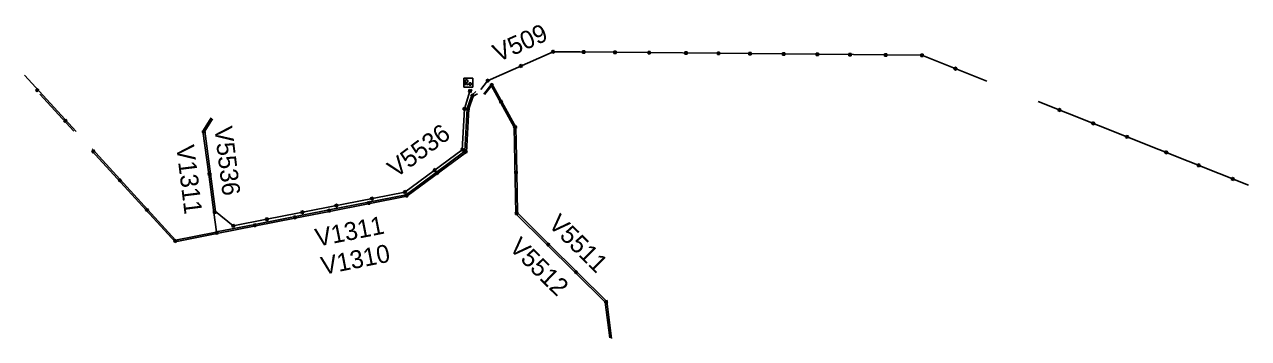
# Model space of a CAD drawing. Extents: x -643369 to -636597, y -1117367 to -1115631.
import ezdxf

# ---------------------------------------------------------------- set-up
doc = ezdxf.new("R2010")
doc.units = 0
for name, color, linetype in [('11', 7, 'Continuous'), ('22', 7, 'Continuous'), ('7', 7, 'Continuous'), ('9', 7, 'Continuous')]:
    doc.layers.add(name, color=color, linetype=linetype)

# ---------------------------------------------------------------- blocks, each defined once
blk = doc.blocks.new('WN200')
at = {"layer": '11'}
for points in [[(-6.3, 6.3), (6.3, 6.3)], [(-6.3, -6.3), (-6.3, 6.3)], [(-4.7, 4.6), (4.7, 4.6)], [(-4.7, -4.8), (-4.7, 4.6)], [(-3.1, 3.2), (3.1, 3.2)], [(-3.1, -3.2), (-3.1, 3.2)], [(-1.6, -1.4), (-1.6, 1.8)], [(-1.6, 1.8), (1.6, 1.8)], [(0, 6.3), (0, 10.1)], [(1.6, 1.8), (1.6, -1.4)], [(3.1, 3.2), (3.1, -3.2)], [(4.7, 4.6), (4.7, -4.8)], [(6.3, 6.3), (6.3, -6.3)], [(6.3, -6.3), (-6.3, -6.3)], [(4.7, -4.8), (-4.7, -4.8)], [(3.1, -3.2), (-3.1, -3.2)], [(1.6, -1.4), (-1.6, -1.4)], [(0, -6.3), (0, -10.1)]]:
    blk.add_lwpolyline(points, dxfattribs=at)
blk = doc.blocks.new('WN600')
at = {"layer": '22'}
for points in [[(25, 25), (-25, 25)], [(-25, 25), (-25, -25)], [(-15.4, 15.4), (-7.1, 15.4)], [(-15.4, -14.2), (-15.4, 15.4)], [(-15.4, 15.4), (-7.1, 15.4)], [(-15.4, -14.2), (-15.4, 15.4)], [(-15.4, 15.4), (-7.1, 15.4)], [(-15.4, -14.2), (-15.4, 15.4)], [(-15.4, 15.4), (-7.1, 15.4)], [(-15.4, -14.2), (-15.4, 15.4)], [(-7.1, 0.4), (-15.4, 0.4)], [(-7.1, 0.4), (-15.4, 0.4)], [(-7.1, 0.4), (-15.4, 0.4)], [(-7.1, 0.4), (-15.4, 0.4)], [(-11.2, 0.4), (-2.1, -14.2)], [(-11.2, 0.4), (-2.1, -14.2)], [(-11.2, 0.4), (-2.1, -14.2)], [(-11.2, 0.4), (-2.1, -14.2)], [(-7.1, 15.4), (-4.6, 13.7)], [(-7.1, 15.4), (-4.6, 13.7)], [(-7.1, 15.4), (-4.6, 13.7)], [(-7.1, 15.4), (-4.6, 13.7)], [(-4.6, 2.5), (-7.1, 0.4)], [(-4.6, 2.5), (-7.1, 0.4)], [(-4.6, 2.5), (-7.1, 0.4)], [(-4.6, 2.5), (-7.1, 0.4)], [(-4.6, 13.7), (-2.1, 10)], [(-4.6, 13.7), (-2.1, 10)], [(-4.6, 13.7), (-2.1, 10)], [(-4.6, 13.7), (-2.1, 10)], [(-2.1, 6.3), (-4.6, 2.5)], [(-2.1, 6.3), (-4.6, 2.5)], [(-2.1, 6.3), (-4.6, 2.5)], [(-2.1, 6.3), (-4.6, 2.5)], [(-2.1, 10), (-2.1, 6.3)], [(-2.1, 10), (-2.1, 6.3)], [(-2.1, 10), (-2.1, 6.3)], [(-2.1, 10), (-2.1, 6.3)], [(25, -25), (25, 25)], [(-25, -25), (25, -25)], [(16.4, -8.3), (16.4, -7.6), (16.3, -6.9), (16.1, -6.2), (15.9, -5.5), (15.6, -4.9), (15.2, -4.3), (14.8, -3.8), (14.3, -3.3), (13.8, -2.9), (13.3, -2.5), (12.7, -2.2), (12.1, -1.9), (11.5, -1.7), (10.8, -1.6), (10.2, -1.6), (9.6, -1.6), (8.9, -1.7), (8.3, -1.9), (7.7, -2.2), (7.1, -2.5), (6.5, -2.9), (6, -3.3), (5.6, -3.8), (5.2, -4.3), (4.8, -4.9), (4.5, -5.5), (4.3, -6.2), (4.1, -6.9), (4, -7.6), (4, -8.3), (4, -9), (4.1, -9.6), (4.3, -10.3), (4.5, -11), (4.8, -11.6), (5.2, -12.2), (5.6, -12.7), (6, -13.2), (6.5, -13.7), (7.1, -14.1), (7.7, -14.4), (8.3, -14.6), (8.9, -14.8), (9.6, -14.9), (10.2, -14.9), (10.8, -14.9), (11.5, -14.8), (12.1, -14.6), (12.7, -14.4), (13.3, -14.1), (13.8, -13.7), (14.3, -13.2), (14.8, -12.7), (15.2, -12.2), (15.6, -11.6), (15.9, -11), (16.1, -10.3), (16.3, -9.6), (16.4, -9), (16.4, -8.3)], [(16.4, -8.3), (16.4, -7.6), (16.3, -6.9), (16.1, -6.2), (15.9, -5.5), (15.6, -4.9), (15.2, -4.3), (14.8, -3.8), (14.3, -3.3), (13.8, -2.9), (13.3, -2.5), (12.7, -2.2), (12.1, -1.9), (11.5, -1.7), (10.8, -1.6), (10.2, -1.6), (9.6, -1.6), (8.9, -1.7), (8.3, -1.9), (7.7, -2.2), (7.1, -2.5), (6.5, -2.9), (6, -3.3), (5.6, -3.8), (5.2, -4.3), (4.8, -4.9), (4.5, -5.5), (4.3, -6.2), (4.1, -6.9), (4, -7.6), (4, -8.3), (4, -9), (4.1, -9.6), (4.3, -10.3), (4.5, -11), (4.8, -11.6), (5.2, -12.2), (5.6, -12.7), (6, -13.2), (6.5, -13.7), (7.1, -14.1), (7.7, -14.4), (8.3, -14.6), (8.9, -14.8), (9.6, -14.9), (10.2, -14.9), (10.8, -14.9), (11.5, -14.8), (12.1, -14.6), (12.7, -14.4), (13.3, -14.1), (13.8, -13.7), (14.3, -13.2), (14.8, -12.7), (15.2, -12.2), (15.6, -11.6), (15.9, -11), (16.1, -10.3), (16.3, -9.6), (16.4, -9), (16.4, -8.3)], [(16.4, -8.3), (16.4, -7.6), (16.3, -6.9), (16.1, -6.2), (15.9, -5.5), (15.6, -4.9), (15.2, -4.3), (14.8, -3.8), (14.3, -3.3), (13.8, -2.9), (13.3, -2.5), (12.7, -2.2), (12.1, -1.9), (11.5, -1.7), (10.8, -1.6), (10.2, -1.6), (9.6, -1.6), (8.9, -1.7), (8.3, -1.9), (7.7, -2.2), (7.1, -2.5), (6.5, -2.9), (6, -3.3), (5.6, -3.8), (5.2, -4.3), (4.8, -4.9), (4.5, -5.5), (4.3, -6.2), (4.1, -6.9), (4, -7.6), (4, -8.3), (4, -9), (4.1, -9.6), (4.3, -10.3), (4.5, -11), (4.8, -11.6), (5.2, -12.2), (5.6, -12.7), (6, -13.2), (6.5, -13.7), (7.1, -14.1), (7.7, -14.4), (8.3, -14.6), (8.9, -14.8), (9.6, -14.9), (10.2, -14.9), (10.8, -14.9), (11.5, -14.8), (12.1, -14.6), (12.7, -14.4), (13.3, -14.1), (13.8, -13.7), (14.3, -13.2), (14.8, -12.7), (15.2, -12.2), (15.6, -11.6), (15.9, -11), (16.1, -10.3), (16.3, -9.6), (16.4, -9), (16.4, -8.3)], [(16.4, -8.3), (16.4, -7.6), (16.3, -6.9), (16.1, -6.2), (15.9, -5.5), (15.6, -4.9), (15.2, -4.3), (14.8, -3.8), (14.3, -3.3), (13.8, -2.9), (13.3, -2.5), (12.7, -2.2), (12.1, -1.9), (11.5, -1.7), (10.8, -1.6), (10.2, -1.6), (9.6, -1.6), (8.9, -1.7), (8.3, -1.9), (7.7, -2.2), (7.1, -2.5), (6.5, -2.9), (6, -3.3), (5.6, -3.8), (5.2, -4.3), (4.8, -4.9), (4.5, -5.5), (4.3, -6.2), (4.1, -6.9), (4, -7.6), (4, -8.3), (4, -9), (4.1, -9.6), (4.3, -10.3), (4.5, -11), (4.8, -11.6), (5.2, -12.2), (5.6, -12.7), (6, -13.2), (6.5, -13.7), (7.1, -14.1), (7.7, -14.4), (8.3, -14.6), (8.9, -14.8), (9.6, -14.9), (10.2, -14.9), (10.8, -14.9), (11.5, -14.8), (12.1, -14.6), (12.7, -14.4), (13.3, -14.1), (13.8, -13.7), (14.3, -13.2), (14.8, -12.7), (15.2, -12.2), (15.6, -11.6), (15.9, -11), (16.1, -10.3), (16.3, -9.6), (16.4, -9), (16.4, -8.3)]]:
    blk.add_lwpolyline(points, dxfattribs=at)

msp = doc.modelspace()

# ---------------------------------------------------------------- linework, layer by layer
at = {"layer": '7'}
for points in [[(-638044.9, -1115944.2), (-638404.5, -1115801.4), (-640295, -1115782.9), (-640445, -1115781.4), (-640807.6, -1115941.8), (-640843.7, -1115990.8)], [(-643369.2, -1115910.6), (-643083.7, -1116222.1)], [(-642306.4, -1116778.2), (-642094.9, -1116736.5), (-641684.3, -1116655.8), (-641257, -1116572.6), (-640932.1, -1116332.1), (-640919.7, -1116095.9), (-640894.9, -1116021.3), (-640871.5, -1116001.6)], [(-642214.1, -1116744), (-642028.5, -1116707.7), (-641264.2, -1116557.6), (-640947.1, -1116323.3), (-640935.1, -1116097.4), (-640904.8, -1115999.2), (-640891.8, -1115990)], [(-640827.5, -1116016), (-640783.2, -1115959), (-640650, -1116197.9), (-640645.8, -1116448.3), (-640641.6, -1116672.7), (-640469.3, -1116843.9), (-640147.5, -1117162.4), (-640121.8, -1117367)], [(-640823.3, -1116018.7), (-640786.2, -1115970.9), (-640659.5, -1116199.3), (-640650.5, -1116677), (-640156.1, -1117166.3), (-640131.2, -1117363.7)], [(-643285, -1116016.1), (-643097, -1116221.1)], [(-642304.8, -1116787.2), (-641872.9, -1116702.1), (-641682.4, -1116664.5), (-641253.4, -1116581), (-640923.5, -1116336.7), (-640910.3, -1116097.8), (-640887.6, -1116026.7), (-640862.1, -1116014.8)], [(-636597.3, -1116519.2), (-637760.4, -1116057.2)], [(-642322.5, -1116670.1), (-642349.8, -1116458.7), (-642382.3, -1116219.9), (-642335.5, -1116146.7)], [(-642329.1, -1116152.4), (-642371.5, -1116221.6), (-642339.4, -1116457.5), (-642312.5, -1116664.2)], [(-642997.5, -1116329.6), (-642536.4, -1116832.4), (-642304.8, -1116787.2)], [(-642995.4, -1116318.4), (-642533.4, -1116822.6), (-642309.4, -1116778.8), (-642306.4, -1116778.2)], [(-642306.4, -1116778.2), (-642322.5, -1116670.1)], [(-642312.5, -1116664.2), (-642214.1, -1116744)]]:
    msp.add_lwpolyline(points, dxfattribs=at)

# ---------------------------------------------------------------- block references
at = {"layer": '11'}
for p, rotation in [((-640445, -1115781.4), 24), ((-640622.8, -1115860), -156.00000000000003), ((-638218.7, -1115875.2), -21.000000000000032), ((-640807.3, -1115941.7), 25), ((-643299, -1115993.9), 133), ((-640904.8, -1115999.2), -107.00000000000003), ((-640784.8, -1115965.1), 119.99999999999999), ((-640891, -1116023.5), 71), ((-640732.9, -1116058.2), -59.99999999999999), ((-640935.1, -1116097.4), 87), ((-640915, -1116096.8), 87), ((-637643.9, -1116103.5), -21.000000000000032), ((-643143.5, -1116163.6), -46.99999999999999), ((-640654.7, -1116198.5), -59.99999999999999), ((-637456.5, -1116177.9), 159), ((-642377.5, -1116223.7), 98), ((-637269.7, -1116252.1), -21.000000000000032), ((-642988.3, -1116332.7), -48.00000000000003), ((-640947.1, -1116323.3), 37), ((-640927.9, -1116334.4), 61), ((-637052.2, -1116338.5), 159), ((-636872.9, -1116409.7), 159), ((-642345.4, -1116458.3), -82), ((-641100.1, -1116436.3), 37), ((-641086.3, -1116451.7), 37), ((-640650.5, -1116448.4), -88.00000000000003), ((-636684.3, -1116484.6), 159), ((-642841.8, -1116492.7), 134), ((-641264.1, -1116557.6), 12), ((-641463.5, -1116617.5), 10.999999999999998), ((-641446.8, -1116593.5), 12), ((-641255.3, -1116576.8), 12), ((-642691.3, -1116656.9), -47.00000000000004), ((-642316.6, -1116669.4), -82), ((-641832.1, -1116669.2), 12), ((-641683.3, -1116660.1), 12), ((-641643.9, -1116632.3), 12), ((-640646.1, -1116674.8), -88.00000000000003), ((-642214.2, -1116744.1), 12), ((-642094.1, -1116741), 12), ((-642028.5, -1116707.7), 10.999999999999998), ((-641873.8, -1116697.6), 12), ((-642534.9, -1116827.7), -14.000000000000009), ((-642305.8, -1116782.9), 12), ((-640471.7, -1116847.8), -44.00000000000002), ((-640318.1, -1116999.8), -44.00000000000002), ((-640151.8, -1117164.4), -82)]:
    msp.add_blockref('WN200', p, dxfattribs=dict(at, rotation=rotation))
for p in [(-640275.3, -1115783), (-640102.7, -1115784.7), (-639913.3, -1115786.6), (-639710.1, -1115788.6), (-639529.5, -1115790.3), (-639355.5, -1115792.1), (-639169.6, -1115793.9), (-638982.2, -1115795.7), (-638801.7, -1115797.5), (-638605.3, -1115799.4), (-638404.5, -1115801.4)]:
    msp.add_blockref('WN200', p, dxfattribs=at)
at = {"layer": '22'}
msp.add_blockref('WN600', (-640914, -1115952), dxfattribs=at)

# ---------------------------------------------------------------- texts
at = {"layer": '9'}
for s, rotation, p in [('V509', 23.91956, (-640749.4, -1115840.4)), ('V5536', 277.03088, (-642319.2, -1116200.2)), ('V5536', 36.50493, (-641314, -1116482.4)), ('V1311', 277.03082, (-642530, -1116303)), ('V5511', 315.24233, (-640476.8, -1116740.6)), ('V1311', 11.12426, (-641749.8, -1116860)), ('V5512', 315.24248, (-640693.3, -1116869.4)), ('V1310', 11.13165, (-641717.6, -1117015.7))]:
    msp.add_text(s, height=99.43, rotation=rotation, dxfattribs=at).set_placement(p)

doc.saveas('drawing.dxf')
